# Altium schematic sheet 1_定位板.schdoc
size 431 x 309 mm; Symbol: Sheet-Symbol_A3; Device: Sheet-Symbol_A3; Convert to PCB: yes; Add into BOM: yes; Company: PhantomRumor; Drawed: PhantomR; @Project Name: 【Styudy】【三键小键盘】CH552G; @Page Count: 1; @Update Date: 2022-08-28; @Create Date: 2022-08-28; @Schematic Name: Schematic1; @Page No: 1; @Page Name: P1
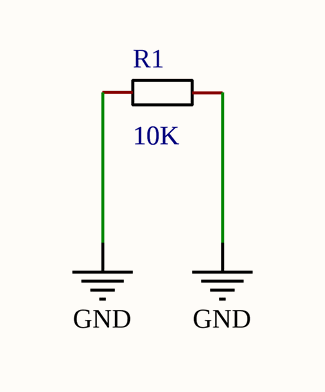
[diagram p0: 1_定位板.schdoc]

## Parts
R1  10K  [R0603]

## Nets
GND: R1.1 R1.2

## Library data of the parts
R1 = Res_0603: Symbol: 电阻; Convert to PCB: yes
